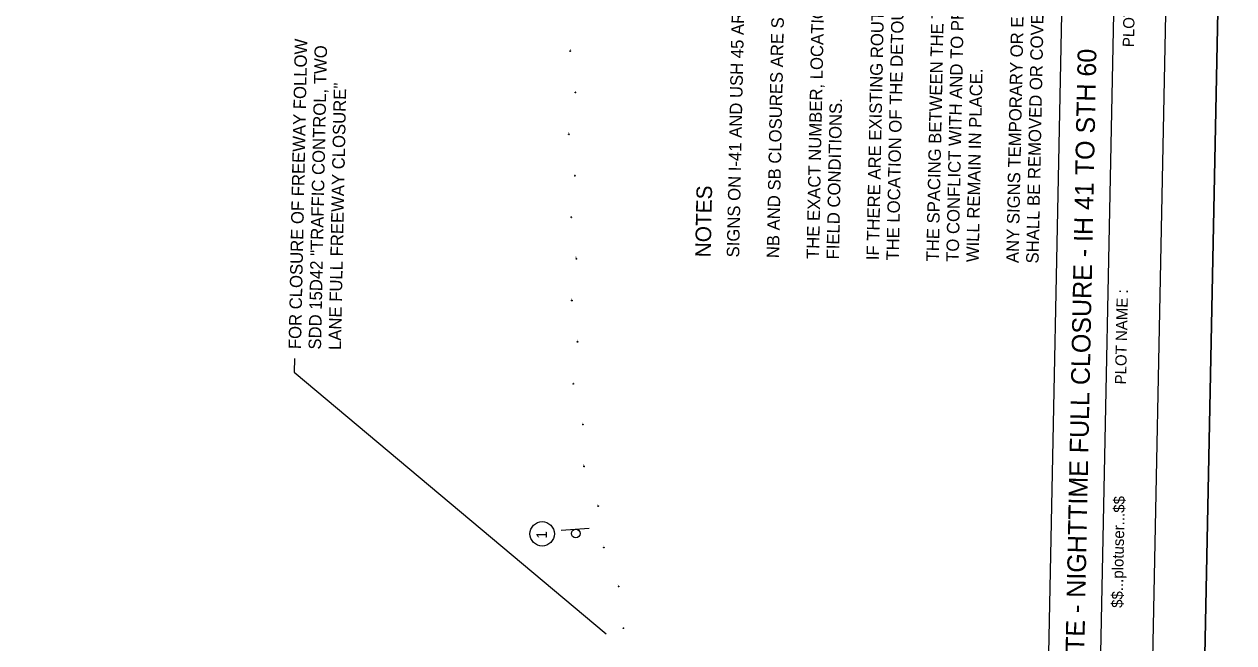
# Model space of a CAD drawing. Extents: x 335726 to 369746, y 119154 to 200788.
# Drawn here: x 352294 to 369746, y 149591 to 158520 of the extents above; entities that cross this region are included whole.
import ezdxf

# ---------------------------------------------------------------- set-up
doc = ezdxf.new("R2010")
doc.units = 0
for name, color, linetype in [('CA-TEXT', 7, 'Continuous'), ('E_SOIL_BORE1 [KAPUR_CADDS_LEVELS]', 7, 'Continuous'), ('E_SOIL_BORE2 [KAPUR_CADDS_LEVELS]', 7, 'Continuous'), ('P_MARK', 7, 'Continuous'), ('P_RDWY_Text', 7, 'Continuous'), ('PLT_Sheet_Border', 7, 'Continuous'), ('PLT_Sheet_Info', 7, 'Continuous'), ('SIGNS-POLES', 7, 'Continuous')]:
    doc.layers.add(name, color=color, linetype=linetype)

msp = doc.modelspace()

# ---------------------------------------------------------------- linework, layer by layer
at = {"layer": 'CA-TEXT'}
for p, q in [((356195, 153693), (356191, 153499)), ((356191, 153499), (360691, 149720))]:
    msp.add_line(p, q, dxfattribs=at)
msp.add_circle((359767, 151164), 176, dxfattribs=at)
at = {"layer": 'P_MARK'}
for p, q in [((360167, 158132), (360177, 158132)), ((360172, 158137), (360172, 158127)), ((360241, 157534), (360251, 157534)), ((360246, 157539), (360246, 157529)), ((360147, 156931), (360157, 156931)), ((360152, 156936), (360152, 156926)), ((360235, 156333), (360245, 156333)), ((360240, 156338), (360240, 156328)), ((360182, 155733), (360192, 155733)), ((360187, 155738), (360187, 155728)), ((360256, 155133), (360266, 155133)), ((360261, 155138), (360261, 155128)), ((360190, 154532), (360200, 154532)), ((360195, 154537), (360195, 154527)), ((360273, 153936), (360283, 153936)), ((360278, 153941), (360278, 153931)), ((360211, 153330), (360221, 153330)), ((360216, 153335), (360216, 153325)), ((360351, 152744), (360361, 152744)), ((360356, 152749), (360356, 152739)), ((360367, 152135), (360377, 152135)), ((360372, 152140), (360372, 152130)), ((360570, 151565), (360580, 151565)), ((360575, 151570), (360575, 151560)), ((360653, 150969), (360663, 150969)), ((360658, 150974), (360658, 150964)), ((360865, 150405), (360875, 150405)), ((360870, 150410), (360870, 150400)), ((360934, 149801), (360944, 149801)), ((360939, 149806), (360939, 149796))]:
    msp.add_line(p, q, dxfattribs=at)
for centre in [(360172, 158132), (360246, 157534), (360152, 156931), (360240, 156333), (360187, 155733), (360261, 155133), (360195, 154532), (360278, 153936), (360216, 153330), (360356, 152744), (360372, 152135), (360575, 151565), (360658, 150969), (360870, 150405), (360939, 149801)]:
    msp.add_circle(centre, 5, dxfattribs=at)
for centre, radius, start, end in [((360172, 158132), 4.5, 89.9869, 179.9869), ((360172, 158132), 4, 89.9869, 179.9869), ((360172, 158132), 3.5, 89.9869, 179.9869), ((360172, 158132), 3, 89.9869, 179.9869), ((360172, 158132), 2.5, 89.9869, 179.9869), ((360172, 158132), 2, 89.9869, 179.9869), ((360172, 158132), 1.5, 89.9869, 179.9869), ((360172, 158132), 1, 89.9869, 179.9869), ((360172, 158132), 0.5, 89.9869, 179.9869), ((360172, 158132), 4.5, 269.9869, 359.9869), ((360172, 158132), 4, 269.9869, 359.9869), ((360172, 158132), 3.5, 269.9869, 359.9869), ((360172, 158132), 3, 269.9869, 359.9869), ((360172, 158132), 2.5, 269.9869, 359.9869), ((360172, 158132), 2, 269.9869, 359.9869), ((360172, 158132), 1.5, 269.9869, 359.9869), ((360172, 158132), 1, 269.9869, 359.9869), ((360172, 158132), 0.5, 269.9869, 359.9869), ((360246, 157534), 4.5, 89.9869, 179.9869), ((360246, 157534), 4, 89.9869, 179.9869), ((360246, 157534), 3.5, 89.9869, 179.9869), ((360246, 157534), 3, 89.9869, 179.9869), ((360246, 157534), 2.5, 89.9869, 179.9869), ((360246, 157534), 2, 89.9869, 179.9869), ((360246, 157534), 1.5, 89.9869, 179.9869), ((360246, 157534), 1, 89.9869, 179.9869), ((360246, 157534), 0.5, 89.9869, 179.9869), ((360246, 157534), 4.5, 269.9869, 359.9869), ((360246, 157534), 4, 269.9869, 359.9869), ((360246, 157534), 3.5, 269.9869, 359.9869), ((360246, 157534), 3, 269.9869, 359.9869), ((360246, 157534), 2.5, 269.9869, 359.9869), ((360246, 157534), 2, 269.9869, 359.9869), ((360246, 157534), 1.5, 269.9869, 359.9869), ((360246, 157534), 1, 269.9869, 359.9869), ((360246, 157534), 0.5, 269.9869, 359.9869), ((360152, 156931), 4.5, 89.9869, 179.9869), ((360152, 156931), 4, 89.9869, 179.9869), ((360152, 156931), 3.5, 89.9869, 179.9869), ((360152, 156931), 3, 89.9869, 179.9869), ((360152, 156931), 2.5, 89.9869, 179.9869), ((360152, 156931), 2, 89.9869, 179.9869), ((360152, 156931), 1.5, 89.9869, 179.9869), ((360152, 156931), 1, 89.9869, 179.9869), ((360152, 156931), 0.5, 89.9869, 179.9869), ((360152, 156931), 4.5, 269.9869, 359.9869), ((360152, 156931), 4, 269.9869, 359.9869), ((360152, 156931), 3.5, 269.9869, 359.9869), ((360152, 156931), 3, 269.9869, 359.9869), ((360152, 156931), 2.5, 269.9869, 359.9869), ((360152, 156931), 2, 269.9869, 359.9869), ((360152, 156931), 1.5, 269.9869, 359.9869), ((360152, 156931), 1, 269.9869, 359.9869), ((360152, 156931), 0.5, 269.9869, 359.9869), ((360240, 156333), 4.5, 89.9869, 179.9869), ((360240, 156333), 4, 89.9869, 179.9869), ((360240, 156333), 3.5, 89.9869, 179.9869), ((360240, 156333), 3, 89.9869, 179.9869), ((360240, 156333), 2.5, 89.9869, 179.9869), ((360240, 156333), 2, 89.9869, 179.9869), ((360240, 156333), 1.5, 89.9869, 179.9869), ((360240, 156333), 1, 89.9869, 179.9869), ((360240, 156333), 4.5, 269.9869, 359.9869), ((360240, 156333), 4, 269.9869, 359.9869), ((360240, 156333), 3.5, 269.9869, 359.9869), ((360240, 156333), 3, 269.9869, 359.9869), ((360240, 156333), 2.5, 269.9869, 359.9869), ((360240, 156333), 2, 269.9869, 359.9869), ((360240, 156333), 1.5, 269.9869, 359.9869), ((360240, 156333), 1, 269.9869, 359.9869), ((360240, 156333), 0.5, 269.9869, 359.9869), ((360240, 156333), 0.5, 89.9869, 179.9869), ((360187, 155733), 4.5, 89.9869, 179.9869), ((360187, 155733), 4, 89.9869, 179.9869), ((360187, 155733), 3.5, 89.9869, 179.9869), ((360187, 155733), 3, 89.9869, 179.9869), ((360187, 155733), 2.5, 89.9869, 179.9869), ((360187, 155733), 2, 89.9869, 179.9869), ((360187, 155733), 1.5, 89.9869, 179.9869), ((360187, 155733), 1, 89.9869, 179.9869), ((360187, 155733), 0.5, 89.9869, 179.9869), ((360187, 155733), 4.5, 269.9869, 359.9869), ((360187, 155733), 4, 269.9869, 359.9869), ((360187, 155733), 3.5, 269.9869, 359.9869), ((360187, 155733), 3, 269.9869, 359.9869), ((360187, 155733), 2.5, 269.9869, 359.9869), ((360187, 155733), 2, 269.9869, 359.9869), ((360187, 155733), 1.5, 269.9869, 359.9869), ((360187, 155733), 1, 269.9869, 359.9869), ((360187, 155733), 0.5, 269.9869, 359.9869), ((360261, 155133), 4.5, 89.9869, 179.9869), ((360261, 155133), 4, 89.9869, 179.9869), ((360261, 155133), 3.5, 89.9869, 179.9869), ((360261, 155133), 3, 89.9869, 179.9869), ((360261, 155133), 2.5, 89.9869, 179.9869), ((360261, 155133), 2, 89.9869, 179.9869), ((360261, 155133), 1.5, 89.9869, 179.9869), ((360261, 155133), 1, 89.9869, 179.9869), ((360261, 155133), 0.5, 89.9869, 179.9869), ((360261, 155133), 4.5, 269.9869, 359.9869), ((360261, 155133), 4, 269.9869, 359.9869), ((360261, 155133), 3.5, 269.9869, 359.9869), ((360261, 155133), 3, 269.9869, 359.9869), ((360261, 155133), 2.5, 269.9869, 359.9869), ((360261, 155133), 2, 269.9869, 359.9869), ((360261, 155133), 1.5, 269.9869, 359.9869), ((360261, 155133), 1, 269.9869, 359.9869), ((360261, 155133), 0.5, 269.9869, 359.9869), ((360195, 154532), 4.5, 89.9869, 179.9869), ((360195, 154532), 4, 89.9869, 179.9869), ((360195, 154532), 3.5, 89.9869, 179.9869), ((360195, 154532), 3, 89.9869, 179.9869), ((360195, 154532), 2.5, 89.9869, 179.9869), ((360195, 154532), 2, 89.9869, 179.9869), ((360195, 154532), 1.5, 89.9869, 179.9869), ((360195, 154532), 1, 89.9869, 179.9869), ((360195, 154532), 0.5, 89.9869, 179.9869), ((360195, 154532), 4.5, 269.9869, 359.9869), ((360195, 154532), 4, 269.9869, 359.9869), ((360195, 154532), 3.5, 269.9869, 359.9869), ((360195, 154532), 3, 269.9869, 359.9869), ((360195, 154532), 2.5, 269.9869, 359.9869), ((360195, 154532), 2, 269.9869, 359.9869), ((360195, 154532), 1.5, 269.9869, 359.9869), ((360195, 154532), 1, 269.9869, 359.9869), ((360195, 154532), 0.5, 269.9869, 359.9869), ((360278, 153936), 4.5, 89.9869, 179.9869), ((360278, 153936), 4, 89.9869, 179.9869), ((360278, 153936), 3.5, 89.9869, 179.9869), ((360278, 153936), 3, 89.9869, 179.9869), ((360278, 153936), 2.5, 89.9869, 179.9869), ((360278, 153936), 2, 89.9869, 179.9869), ((360278, 153936), 1.5, 89.9869, 179.9869), ((360278, 153936), 1, 89.9869, 179.9869), ((360278, 153936), 0.5, 89.9869, 179.9869), ((360278, 153936), 4.5, 269.9869, 359.9869), ((360278, 153936), 4, 269.9869, 359.9869), ((360278, 153936), 3.5, 269.9869, 359.9869), ((360278, 153936), 3, 269.9869, 359.9869), ((360278, 153936), 2.5, 269.9869, 359.9869), ((360278, 153936), 2, 269.9869, 359.9869), ((360278, 153936), 1.5, 269.9869, 359.9869), ((360278, 153936), 1, 269.9869, 359.9869), ((360278, 153936), 0.5, 269.9869, 359.9869), ((360216, 153330), 4.5, 89.9869, 179.9869), ((360216, 153330), 4, 89.9869, 179.9869), ((360216, 153330), 3.5, 89.9869, 179.9869), ((360216, 153330), 3, 89.9869, 179.9869), ((360216, 153330), 2.5, 89.9869, 179.9869), ((360216, 153330), 2, 89.9869, 179.9869), ((360216, 153330), 1.5, 89.9869, 179.9869), ((360216, 153330), 1, 89.9869, 179.9869), ((360216, 153330), 0.5, 89.9869, 179.9869), ((360216, 153330), 4.5, 269.9869, 359.9869), ((360216, 153330), 4, 269.9869, 359.9869), ((360216, 153330), 3.5, 269.9869, 359.9869), ((360216, 153330), 3, 269.9869, 359.9869), ((360216, 153330), 2.5, 269.9869, 359.9869), ((360216, 153330), 2, 269.9869, 359.9869), ((360216, 153330), 1.5, 269.9869, 359.9869), ((360216, 153330), 1, 269.9869, 359.9869), ((360216, 153330), 0.5, 269.9869, 359.9869), ((360356, 152744), 4.5, 89.9869, 179.9869), ((360356, 152744), 4, 89.9869, 179.9869), ((360356, 152744), 3.5, 89.9869, 179.9869), ((360356, 152744), 3, 89.9869, 179.9869), ((360356, 152744), 2.5, 89.9869, 179.9869), ((360356, 152744), 2, 89.9869, 179.9869), ((360356, 152744), 1.5, 89.9869, 179.9869), ((360356, 152744), 1, 89.9869, 179.9869), ((360356, 152744), 0.5, 89.9869, 179.9869), ((360356, 152744), 4.5, 269.9869, 359.9869), ((360356, 152744), 4, 269.9869, 359.9869), ((360356, 152744), 3.5, 269.9869, 359.9869), ((360356, 152744), 3, 269.9869, 359.9869), ((360356, 152744), 2.5, 269.9869, 359.9869), ((360356, 152744), 2, 269.9869, 359.9869), ((360356, 152744), 1.5, 269.9869, 359.9869), ((360356, 152744), 1, 269.9869, 359.9869), ((360356, 152744), 0.5, 269.9869, 359.9869), ((360372, 152135), 4.5, 89.9869, 179.9869), ((360372, 152135), 4, 89.9869, 179.9869), ((360372, 152135), 3.5, 89.9869, 179.9869), ((360372, 152135), 3, 89.9869, 179.9869), ((360372, 152135), 2.5, 89.9869, 179.9869), ((360372, 152135), 2, 89.9869, 179.9869), ((360372, 152135), 1.5, 89.9869, 179.9869), ((360372, 152135), 1, 89.9869, 179.9869), ((360372, 152135), 0.5, 89.9869, 179.9869), ((360372, 152135), 4.5, 269.9869, 359.9869), ((360372, 152135), 4, 269.9869, 359.9869), ((360372, 152135), 3.5, 269.9869, 359.9869), ((360372, 152135), 3, 269.9869, 359.9869), ((360372, 152135), 2.5, 269.9869, 359.9869), ((360372, 152135), 2, 269.9869, 359.9869), ((360372, 152135), 1.5, 269.9869, 359.9869), ((360372, 152135), 1, 269.9869, 359.9869), ((360372, 152135), 0.5, 269.9869, 359.9869), ((360575, 151565), 4.5, 89.9869, 179.9869), ((360575, 151565), 4, 89.9869, 179.9869), ((360575, 151565), 3.5, 89.9869, 179.9869), ((360575, 151565), 3, 89.9869, 179.9869), ((360575, 151565), 2.5, 89.9869, 179.9869), ((360575, 151565), 2, 89.9869, 179.9869), ((360575, 151565), 1.5, 89.9869, 179.9869), ((360575, 151565), 1, 89.9869, 179.9869), ((360575, 151565), 0.5, 89.9869, 179.9869), ((360575, 151565), 4.5, 269.9869, 359.9869), ((360575, 151565), 4, 269.9869, 359.9869), ((360575, 151565), 3.5, 269.9869, 359.9869), ((360575, 151565), 3, 269.9869, 359.9869), ((360575, 151565), 2.5, 269.9869, 359.9869), ((360575, 151565), 2, 269.9869, 359.9869), ((360575, 151565), 1.5, 269.9869, 359.9869), ((360575, 151565), 1, 269.9869, 359.9869), ((360575, 151565), 0.5, 269.9869, 359.9869), ((360658, 150969), 4.5, 89.9869, 179.9869), ((360658, 150969), 4, 89.9869, 179.9869), ((360658, 150969), 3.5, 89.9869, 179.9869), ((360658, 150969), 3, 89.9869, 179.9869), ((360658, 150969), 2.5, 89.9869, 179.9869), ((360658, 150969), 2, 89.9869, 179.9869), ((360658, 150969), 1.5, 89.9869, 179.9869), ((360658, 150969), 1, 89.9869, 179.9869), ((360658, 150969), 0.5, 89.9869, 179.9869), ((360658, 150969), 4.5, 269.9869, 359.9869), ((360658, 150969), 4, 269.9869, 359.9869), ((360658, 150969), 3.5, 269.9869, 359.9869), ((360658, 150969), 3, 269.9869, 359.9869), ((360658, 150969), 2.5, 269.9869, 359.9869), ((360658, 150969), 2, 269.9869, 359.9869), ((360658, 150969), 1.5, 269.9869, 359.9869), ((360658, 150969), 1, 269.9869, 359.9869), ((360658, 150969), 0.5, 269.9869, 359.9869), ((360870, 150405), 4.5, 89.9869, 179.9869), ((360870, 150405), 4, 89.9869, 179.9869), ((360870, 150405), 3.5, 89.9869, 179.9869), ((360870, 150405), 3, 89.9869, 179.9869), ((360870, 150405), 2.5, 89.9869, 179.9869), ((360870, 150405), 2, 89.9869, 179.9869), ((360870, 150405), 1.5, 89.9869, 179.9869), ((360870, 150405), 1, 89.9869, 179.9869), ((360870, 150405), 0.5, 89.9869, 179.9869), ((360870, 150405), 4.5, 269.9869, 359.9869), ((360870, 150405), 4, 269.9869, 359.9869), ((360870, 150405), 3.5, 269.9869, 359.9869), ((360870, 150405), 3, 269.9869, 359.9869), ((360870, 150405), 2.5, 269.9869, 359.9869), ((360870, 150405), 2, 269.9869, 359.9869), ((360870, 150405), 1.5, 269.9869, 359.9869), ((360870, 150405), 1, 269.9869, 359.9869), ((360870, 150405), 0.5, 269.9869, 359.9869), ((360939, 149801), 4.5, 89.9869, 179.9869), ((360939, 149801), 4, 89.9869, 179.9869), ((360939, 149801), 3.5, 89.9869, 179.9869), ((360939, 149801), 3, 89.9869, 179.9869), ((360939, 149801), 2.5, 89.9869, 179.9869), ((360939, 149801), 2, 89.9869, 179.9869), ((360939, 149801), 1.5, 89.9869, 179.9869), ((360939, 149801), 1, 89.9869, 179.9869), ((360939, 149801), 0.5, 89.9869, 179.9869), ((360939, 149801), 4.5, 269.9869, 359.9869), ((360939, 149801), 4, 269.9869, 359.9869), ((360939, 149801), 3.5, 269.9869, 359.9869), ((360939, 149801), 3, 269.9869, 359.9869), ((360939, 149801), 2.5, 269.9869, 359.9869), ((360939, 149801), 2, 269.9869, 359.9869), ((360939, 149801), 1.5, 269.9869, 359.9869), ((360939, 149801), 1, 269.9869, 359.9869), ((360939, 149801), 0.5, 269.9869, 359.9869)]:
    msp.add_arc(centre, radius, start, end, dxfattribs=at)
at = {"layer": 'P_RDWY_Text'}
msp.add_lwpolyline([(335726, 119818), (336753, 170808), (369746, 170144), (368719, 119154)], close=True, dxfattribs=at)
at = {"layer": 'PLT_Sheet_Border'}
for points in [[(368719, 119154), (369746, 170144), (336753, 170808), (335726, 119818)], [(367976, 119529), (368976, 169169), (337483, 169803), (336483, 120163)]]:
    msp.add_lwpolyline(points, close=True, dxfattribs=at)
at = {"layer": 'PLT_Sheet_Info'}
for p, q in [((366508, 121096), (367459, 168337)), ((367258, 121081), (368209, 168322))]:
    msp.add_line(p, q, dxfattribs=at)
at = {"layer": 'SIGNS-POLES'}
for p, q in [((360041, 151215), (360242, 151232)), ((360244, 151231), (360446, 151247))]:
    msp.add_line(p, q, dxfattribs=at)
msp.add_circle((360251, 151169), 62.6, dxfattribs=at)

# ---------------------------------------------------------------- texts
at = {"layer": 'CA-TEXT'}
for s, height, rotation, p in [('THE SPACING BETWEEN THE TRAFFIC CONTROL AND DETOUR SIGNS SHOULD BE ADJUSTED NOT', 180, 88.8462, (365489, 155094)), ("TO CONFLICT WITH AND TO PROVIDE A MINIMUM OF 200' CLEARANCE TO EXISTING SIGNS THAT", 180, 88.8462, (365777, 155088)), ('IF THERE ARE EXISTING ROUTE MARKER ASSEMBLIES THAT WILL REMAIN IN PLACE, ADJUST', 180, 88.8462, (364625, 155112)), ('THE LOCATION OF THE DETOUR SIGNS TO CORRESPOND WITH THE EXISTING ASSEMBLIES. ', 180, 88.8462, (364913, 155106)), ('NB AND SB CLOSURES ARE SHOWN BUT ONLY ONE DIRECTION CAN BE CLOSED AT A TIME.', 180, 88.8462, (363185, 155141)), ('ANY SIGNS TEMPORARY OR EXISTING, WHICH CONFLICT WITH TRAFFIC CONTROL "IN USE",', 180, 88.8462, (366641, 155071)), ('THE EXACT NUMBER, LOCATION AND SPACING OF ALL SIGNS SHALL BE ADJUSTED TO FIT', 180, 88.8462, (363761, 155129)), ('SHALL BE REMOVED OR COVERED AS NEEDED AND AS APPROVED BY THE ENGINEER.', 180, 88.8462, (366929, 155065)), ('SIGNS ON I-41 AND USH 45 ARE SIZE 3.  SIGNS ON ALL OTHER ROADS ARE SIZE 2.', 180, 88.8462, (362610, 155152)), ('FOR CLOSURE OF FREEWAY FOLLOW', 180, 88.8468, (356288, 153828)), ('SDD 15D42 "TRAFFIC CONTROL, TWO', 180, 88.8468, (356576, 153822)), ('WILL REMAIN IN PLACE.', 180, 88.8462, (366065, 155083)), ('LANE FULL FREEWAY CLOSURE"', 180, 88.8468, (356864, 153816)), ('FIELD CONDITIONS.', 180, 88.8462, (364049, 155123)), ('NOTES', 225, 88.8468, (362199, 155153)), ('1', 150, 88.8468, (359834, 151091))]:
    msp.add_text(s, height=height, rotation=rotation, dxfattribs=at).set_placement(p)
at = {"layer": 'E_SOIL_BORE1 [KAPUR_CADDS_LEVELS]'}
for s, rotation, p in [('B50', 90.6368, (360245, 156339)), ('B47', 90.6368, (360199, 155741)), ('B48', 90.6368, (360257, 155139)), ('B43', 98.8576, (360219, 153339)), ('B44', 98.8576, (360359, 152751)), ('B41', 98.8576, (360375, 152145)), ('B40', 105.7466, (360873, 150413)), ('B37', 105.7466, (360943, 149811))]:
    msp.add_text(s, height=10, rotation=rotation, dxfattribs=at).set_placement(p)
at = {"layer": 'E_SOIL_BORE2 [KAPUR_CADDS_LEVELS]'}
for s, rotation, p in [('B51', 90.6368, (360177, 158139)), ('B52', 90.6368, (360251, 157541)), ('B49', 90.6368, (360156, 156938)), ('B48', 90.6368, (360264, 155140)), ('B45', 90.6368, (360199, 154541)), ('B46', 90.6368, (360283, 153943)), ('B41', 105.7466, (360373, 152146)), ('B42', 105.7466, (360577, 151574)), ('B39', 105.7466, (360660, 150978))]:
    msp.add_text(s, height=10, rotation=rotation, dxfattribs=at).set_placement(p)
at = {"layer": 'PLT_Sheet_Info'}
for s, height, p in [('PLOT SCALE : ', 162, (368305, 158187)), ('DETOUR ROUTE - NIGHTTIME FULL CLOSURE - IH 41 TO STH 60                ', 270, (367540, 147031)), ('PLOT NAME :                      ', 162, (368192, 153319)), ('$$...plotuser...$$', 162, (368142, 150094))]:
    msp.add_text(s, height=height, rotation=88.8462, dxfattribs=at).set_placement(p)

doc.saveas('drawing.dxf')
